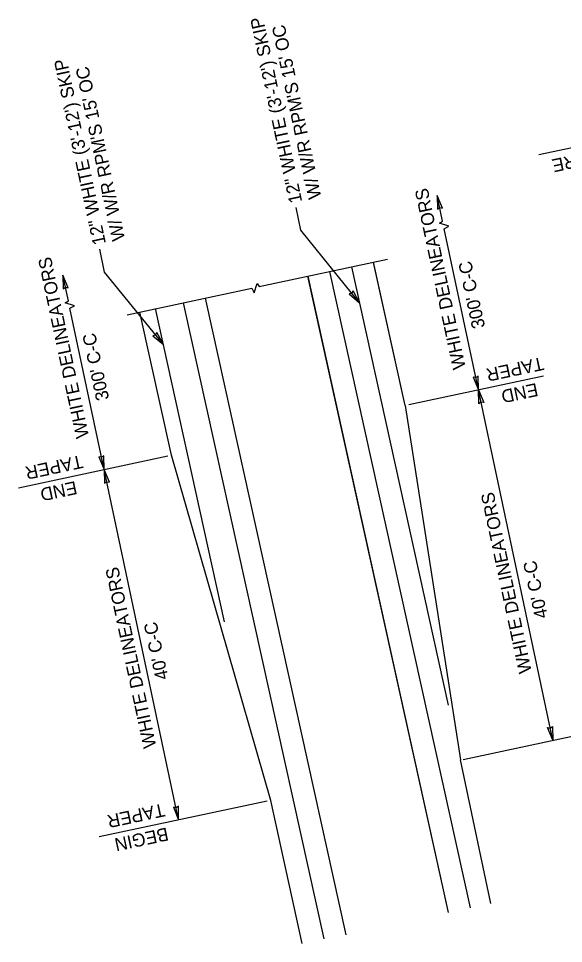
# Model space of a CAD drawing. Extents: x 578088 to 579220, y 1508751 to 1510399.
# Drawn here: x 578126.2 to 578418.2, y 1508750.8 to 1509246 of the extents above; entities that cross this region are included whole.
import ezdxf

# ---------------------------------------------------------------- set-up
doc = ezdxf.new("R2010")
doc.units = 0
for name, color, linetype in [('18', 7, 'Continuous'), ('19', 7, 'Continuous'), ('2', 7, 'Continuous'), ('41', 7, 'Continuous'), ('52', 7, 'Continuous')]:
    doc.layers.add(name, color=color, linetype=linetype)

msp = doc.modelspace()

# ---------------------------------------------------------------- linework, layer by layer
at = {"layer": '18'}
for p, q in [((578356.64, 1508878.44), (578304.75, 1509113.07)), ((578316.3, 1509115.42), (578333.24, 1509038.78)), ((578356.71, 1508767.44), (578281.41, 1509108.01)), ((578368.34, 1508769.92), (578293.04, 1509110.48)), ((578290.03, 1508753.27), (578214.73, 1509093.83)), ((578236.68, 1508923), (578199.6, 1509090.72)), ((578333.41, 1509038.81), (578363.06, 1508849.04))]:
    msp.add_line(p, q, dxfattribs=at)
at = {"layer": '19'}
msp.add_line((578379.39, 1508772.26), (578363.06, 1508849.04), dxfattribs=at)
at = {"layer": '2'}
for p, q in [((578333.41, 1509038.81), (578316.46, 1509115.46)), ((578356.55, 1508767.41), (578281.25, 1509107.97))]:
    msp.add_line(p, q, dxfattribs=at)
at = {"layer": '41'}
for p, q in [((578301.83, 1508755.5), (578226.47, 1509096.33)), ((578208.2, 1509012.2), (578191.25, 1509088.84)), ((578261.35, 1508827.42), (578208.2, 1509012.2)), ((578278.3, 1508750.78), (578261.35, 1508827.42))]:
    msp.add_line(p, q, dxfattribs=at)
at = {"layer": '52'}
for p, q in [((578405.02, 1509173.15), (578542.9, 1509202.46)), ((578353.45, 1509137.49), (578350.52, 1509151.28)), ((578350.52, 1509151.28), (578350.65, 1509143.9)), ((578353.34, 1509144.47), (578350.52, 1509151.28)), ((578277.54, 1509132.6), (578274.94, 1509144.85)), ((578350.65, 1509143.9), (578351.91, 1509144.73)), ((578351.91, 1509144.73), (578353.34, 1509144.47)), ((578351.82, 1509136.37), (578353.45, 1509137.49)), ((578356.73, 1509134.8), (578351.82, 1509136.37)), ((578309.03, 1509093.75), (578277.54, 1509132.6)), ((578354.31, 1509133.44), (578356.73, 1509134.8)), ((578354.31, 1509133.44), (578354.31, 1509133.44)), ((578372.65, 1509047.15), (578354.31, 1509133.44)), ((578172.38, 1509110.25), (578169.78, 1509122.5)), ((578255.26, 1509102.45), (578324.01, 1509117.06)), ((578152.95, 1509094.87), (578150.02, 1509108.66)), ((578150.02, 1509108.66), (578150.16, 1509101.28)), ((578152.85, 1509101.85), (578150.02, 1509108.66)), ((578203.87, 1509071.4), (578172.38, 1509110.25)), ((578150.16, 1509101.28), (578151.41, 1509102.11)), ((578151.41, 1509102.11), (578152.85, 1509101.85)), ((578184.4, 1509087.39), (578251.21, 1509101.59)), ((578251.21, 1509101.59), (578251.21, 1509101.59)), ((578251.21, 1509101.59), (578252.56, 1509099.16)), ((578252.56, 1509099.16), (578254.14, 1509104.07)), ((578254.14, 1509104.07), (578255.26, 1509102.45)), ((578304.81, 1509098.96), (578303.41, 1509098.53)), ((578303.41, 1509098.53), (578309.03, 1509093.75)), ((578305.55, 1509100.26), (578304.81, 1509098.96)), ((578309.03, 1509093.75), (578305.55, 1509100.26)), ((578151.33, 1509093.75), (578152.95, 1509094.87)), ((578156.24, 1509092.18), (578151.33, 1509093.75)), ((578153.81, 1509090.83), (578156.24, 1509092.18)), ((578153.81, 1509090.83), (578153.81, 1509090.83)), ((578172.15, 1509004.54), (578153.81, 1509090.83)), ((578199.65, 1509076.6), (578198.25, 1509076.18)), ((578200.39, 1509077.91), (578199.65, 1509076.6)), ((578203.87, 1509071.4), (578200.39, 1509077.91)), ((578198.25, 1509076.18), (578203.87, 1509071.4)), ((578407.45, 1509054.55), (578335.32, 1509039.22)), ((578371.26, 1509053.71), (578369.82, 1509053.97)), ((578369.82, 1509053.97), (578372.65, 1509047.15)), ((578372.51, 1509054.54), (578371.26, 1509053.71)), ((578372.65, 1509047.15), (578372.51, 1509054.54)), ((578412.52, 1508859.55), (578372.65, 1509047.15)), ((578372.65, 1509047.15), (578375.53, 1509040.35)), ((578372.83, 1509039.78), (578372.65, 1509047.15)), ((578374.04, 1509040.6), (578372.83, 1509039.78)), ((578375.53, 1509040.35), (578374.04, 1509040.6)), ((578126.24, 1508994.78), (578206.24, 1509011.78)), ((578170.76, 1509011.09), (578169.33, 1509011.35)), ((578169.33, 1509011.35), (578172.15, 1509004.54)), ((578172.02, 1509011.92), (578170.76, 1509011.09)), ((578172.15, 1509004.54), (578172.02, 1509011.92)), ((578212.03, 1508816.94), (578172.15, 1509004.54)), ((578172.15, 1509004.54), (578172.29, 1508997.15)), ((578174.98, 1508997.73), (578172.15, 1509004.54)), ((578172.29, 1508997.15), (578173.55, 1508997.98)), ((578173.55, 1508997.98), (578174.98, 1508997.73)), ((578364.55, 1508849.36), (578517.28, 1508881.82)), ((578412.52, 1508859.55), (578409.65, 1508866.35)), ((578409.65, 1508866.35), (578411.13, 1508866.11)), ((578411.13, 1508866.11), (578412.34, 1508866.93)), ((578412.34, 1508866.93), (578412.52, 1508859.55)), ((578259.39, 1508827.01), (578169.53, 1508807.91)), ((578211.89, 1508824.32), (578210.64, 1508823.49)), ((578212.03, 1508816.94), (578211.89, 1508824.32)), ((578210.64, 1508823.49), (578209.2, 1508823.75)), ((578209.2, 1508823.75), (578212.03, 1508816.94))]:
    msp.add_line(p, q, dxfattribs=at)

# ---------------------------------------------------------------- texts
at = {"layer": '18'}
for p in [(578376.3, 1509080.8), (578174.87, 1509042.26)]:
    msp.add_text("300' C-C", height=7, rotation=102, dxfattribs=at).set_placement(p)
at = {"layer": '52'}
for s, rotation, p in [('12" WHITE (3\'-12\') SKIP', 102, (578278.29, 1509147.94)), ("W/ W/R RPM'S 15' OC", 102, (578288.56, 1509150.12)), ('12" WHITE (3\'-12\') SKIP', 102, (578173.13, 1509125.58)), ("W/ W/R RPM'S 15' OC", 102, (578183.4, 1509127.77)), ('THEORETICAL GORE', 192, (578505.14, 1509190.33)), ('WHITE DELINEATORS', 102, (578365.92, 1509058.96)), ('WHITE DELINEATORS', 102, (578164.08, 1509022.13)), ('TAPER', 192, (578406.83, 1509064.85)), ('END', 192, (578403.71, 1509050.9)), ('TAPER', 192, (578159.85, 1509012.36)), ('END', 192, (578156.73, 1508998.4)), ('WHITE DELINEATORS', 102, (578401.3, 1508896.2)), (" 40' C-C", 102, (578410.44, 1508922.99)), ('WHITE DELINEATORS', 102, (578200.14, 1508856.17)), (" 40' C-C", 102, (578207.2, 1508890.17)), ('TAPER', 192, (578203.77, 1508825.84)), ('BEGIN', 192, (578205.7, 1508812.96))]:
    msp.add_text(s, height=7, rotation=rotation, dxfattribs=at).set_placement(p)

doc.saveas('drawing.dxf')
